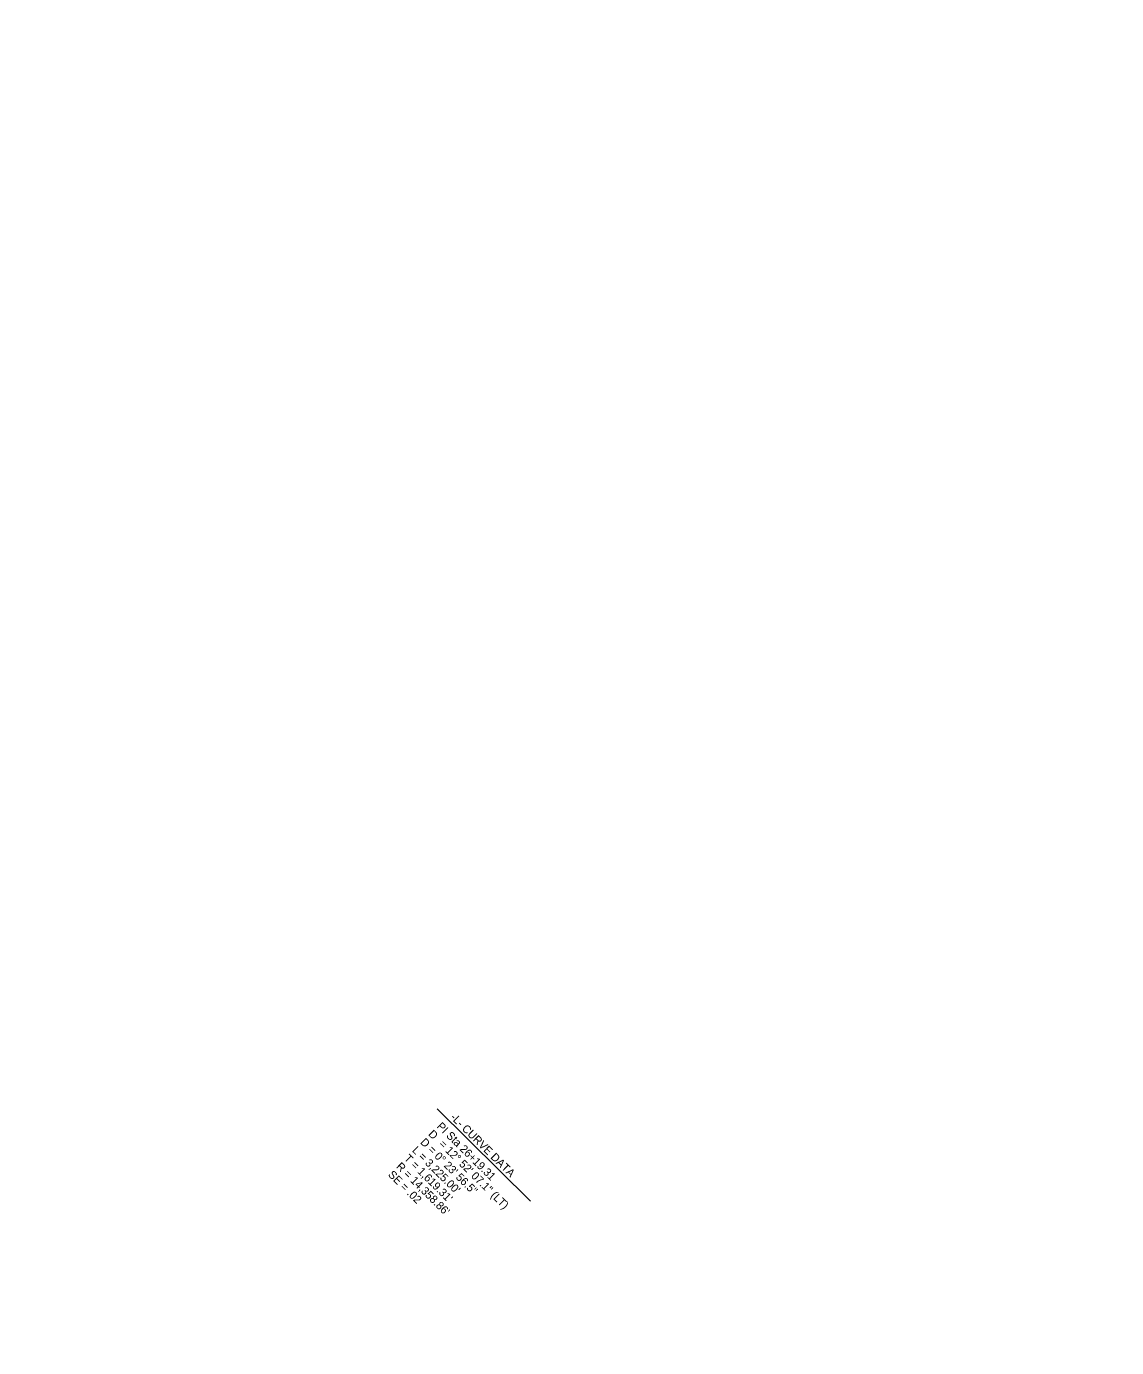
# Model space of a CAD drawing. Extents: x 1602281 to 1604813, y 908112 to 910586.
# Drawn here: x 1603569 to 1604523, y 909268 to 910424 of the extents above; entities that cross this region are included whole.
import ezdxf

# ---------------------------------------------------------------- set-up
doc = ezdxf.new("R2010")
doc.units = 0
for name, color, linetype in [('Exist Environmental Endangered Plant Boundary Cogo Point CELL', 7, 'Continuous'), ('Exist Hydro Jurisdictional Stream or Body of Water NEU Mitigable Cogo Point CELL', 7, 'Continuous'), ('Exist Hydro Jurisdictional Stream or Body of Water NEU NonMitigable', 7, 'Continuous')]:
    doc.layers.add(name, color=color, linetype=linetype)

msp = doc.modelspace()

# ---------------------------------------------------------------- linework, layer by layer
at = {"layer": 'Exist Environmental Endangered Plant Boundary Cogo Point CELL'}
msp.add_line((1603928.9, 909477.1), (1604010.4, 909396.4), dxfattribs=at)
at = {"layer": 'Exist Hydro Jurisdictional Stream or Body of Water NEU Mitigable Cogo Point CELL'}
msp.add_arc((1613646.3, 919202), 14358.9, 217.68536, 230.55399, dxfattribs=at)
at = {"layer": 'Exist Hydro Jurisdictional Stream or Body of Water NEU NonMitigable'}
msp.add_arc((1613646.3, 919202), 14358.9, 217.68536, 230.55399, dxfattribs=at)

# ---------------------------------------------------------------- texts
at = {"layer": 'Exist Environmental Endangered Plant Boundary Cogo Point CELL'}
for s, rotation, p in [('PI Sta 26+19.31', 315.2976, (1603928, 909461.1)), ('-L- CURVE DATA', 315.2975, (1603939.9, 909469)), ('D = 0%%d 23\' 56.5"', 315.2976, (1603913.5, 909447.3)), ('D', 315.2976, (1603920.5, 909454.4)), ('= 12%%d 52\' 07.1" (LT)', 315.2976, (1603929.8, 909445.6)), ("T = 1,619.31'", 315.2976, (1603899.4, 909433.1)), ("L = 3,225.00'", 315.2976, (1603906.4, 909440.2)), ("R = 14,358.86'", 315.2976, (1603892.4, 909426)), ('SE = .02', 315.2976, (1603885.3, 909418.9))]:
    msp.add_text(s, height=7, rotation=rotation, dxfattribs=at).set_placement(p)

doc.saveas('drawing.dxf')
